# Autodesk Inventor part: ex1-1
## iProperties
Company: MOSS DESIGNS
Shininess: 64.0
Length Units: 11272
Angle Units: 11279
Time Units: 11290
Mass Units: 11286
Length Display Precision: 3
Angle Display Precision: 2
Compacted: True
Part Number: ex1-1
Document SubType Name: Modeling
Created: 2003-11
Designer: Elise Moss
Cost Center: 0.4 lbmass
Authority: 11.8 in^3
Manufacturer: Standard
Standards Organization: Custom
Description: BLOCK
Density: 0.0
Volumn: 0.0
Area: 0.0
PropertySet Name: Model Information
Control State: 0
Master: False
Checked Out: False
SaveDate: 2003-11-10
SaveTime: 19:42
TotalMass: 0.4 lbmass
TotalVolume: 11.8 in^3
Author: Elise Moss
Title: BLOCK
Revision Number: A
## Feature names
1. Extrusion1
